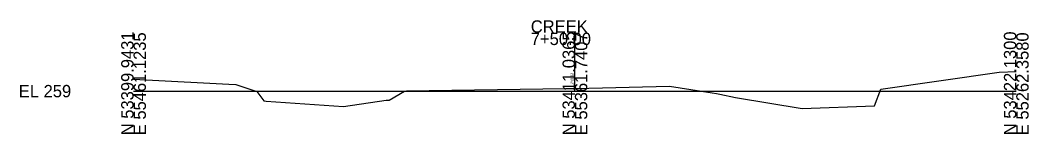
# Model space of a CAD drawing. Extents: x 7498 to 7727, y 91719 to 100242.
# Drawn here: x 7498.3 to 7726.8, y 93219.2 to 93244.9 of the extents above; entities that cross this region are included whole.
import ezdxf

# ---------------------------------------------------------------- set-up
doc = ezdxf.new("R2010")
doc.units = 0
for name, color, linetype in [('Level 10', 7, 'Continuous'), ('Level 60', 7, 'Continuous'), ('Level 63', 7, 'Continuous')]:
    doc.layers.add(name, color=color, linetype=linetype)

msp = doc.modelspace()

# ---------------------------------------------------------------- linework, layer by layer
at = {"layer": 'Level 60'}
for p, q in [((7693.28, 93229.28), (7720.12, 93233.18)), ((7720.12, 93233.18), (7723.99, 93233.27)), ((7523.99, 93231.58), (7526.82, 93231.4)), ((7526.82, 93231.4), (7545.6, 93230.42)), ((7545.6, 93230.42), (7547.13, 93230.33)), ((7547.13, 93230.33), (7551.91, 93228.8)), ((7551.91, 93228.8), (7553.49, 93226.68)), ((7581.93, 93226.78), (7585.37, 93228.82)), ((7585.37, 93228.82), (7585.8, 93228.89)), ((7585.8, 93228.89), (7621.85, 93229.45)), ((7621.85, 93229.45), (7624.13, 93229.48)), ((7624.13, 93229.48), (7645.43, 93229.95)), ((7645.43, 93229.95), (7655.09, 93228.49)), ((7655.09, 93228.49), (7656.09, 93228.34)), ((7656.09, 93228.34), (7656.83, 93228.17)), ((7691.9, 93225.49), (7693.28, 93229.28)), ((7553.49, 93226.68), (7554.05, 93226.6)), ((7554.05, 93226.6), (7571.57, 93225.35)), ((7571.57, 93225.35), (7581.22, 93226.83)), ((7581.22, 93226.83), (7581.93, 93226.78)), ((7656.83, 93228.17), (7660.35, 93227.37)), ((7660.35, 93227.37), (7675.45, 93224.9)), ((7675.45, 93224.9), (7691.9, 93225.49))]:
    msp.add_line(p, q, dxfattribs=at)
at = {"layer": 'Level 63'}
for p, q in [((7623.99, 93228.85), (7623.99, 93242.1)), ((7523.99, 93228.85), (7623.99, 93228.85)), ((7623.99, 93228.85), (7723.99, 93228.85))]:
    msp.add_line(p, q, dxfattribs=at)

# ---------------------------------------------------------------- texts
at = {"layer": 'Level 10'}
msp.add_text('259.63', height=0.6, rotation=90, dxfattribs=at).set_placement((7623.59, 93230.48))
at = {"layer": 'Level 63'}
for s, p in [('CREEK', (7613.99, 93242.1)), ('7+50.00', (7613.99, 93239.3)), ('EL 259', (7497.99, 93227.45))]:
    msp.add_text(s, height=2.8, dxfattribs=at).set_placement(p)
for s, p in [('N 53399.9431', (7523.99, 93218.85)), ('E 55461.1235', (7526.79, 93218.85)), ('N 53411.0365', (7623.99, 93218.85)), ('E 55361.7407', (7626.79, 93218.85)), ('N 53422.1300', (7723.99, 93218.85)), ('E 55262.3580', (7726.79, 93218.85))]:
    msp.add_text(s, height=2.8, rotation=90, dxfattribs=at).set_placement(p)

doc.saveas('drawing.dxf')
